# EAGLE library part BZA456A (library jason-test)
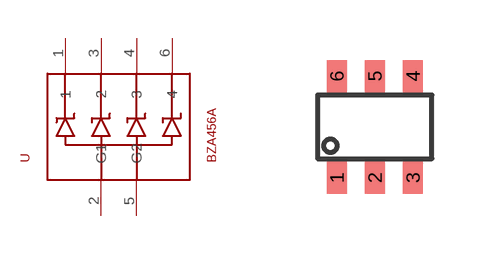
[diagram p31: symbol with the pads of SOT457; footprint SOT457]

Designator prefix -

## BZA456A  [SOT457]
1  1
2  G1  pwr
3  2
4  3
5  G2  pwr
6  4

## Footprint SOT457 (pad centres in mm)
smd 0.5 x 0.8: 1 -0.953,-1.27; 2 0,-1.27; 3 0.953,-1.27; 4 0.953,1.27; 5 0,1.27; 6 -0.953,1.27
